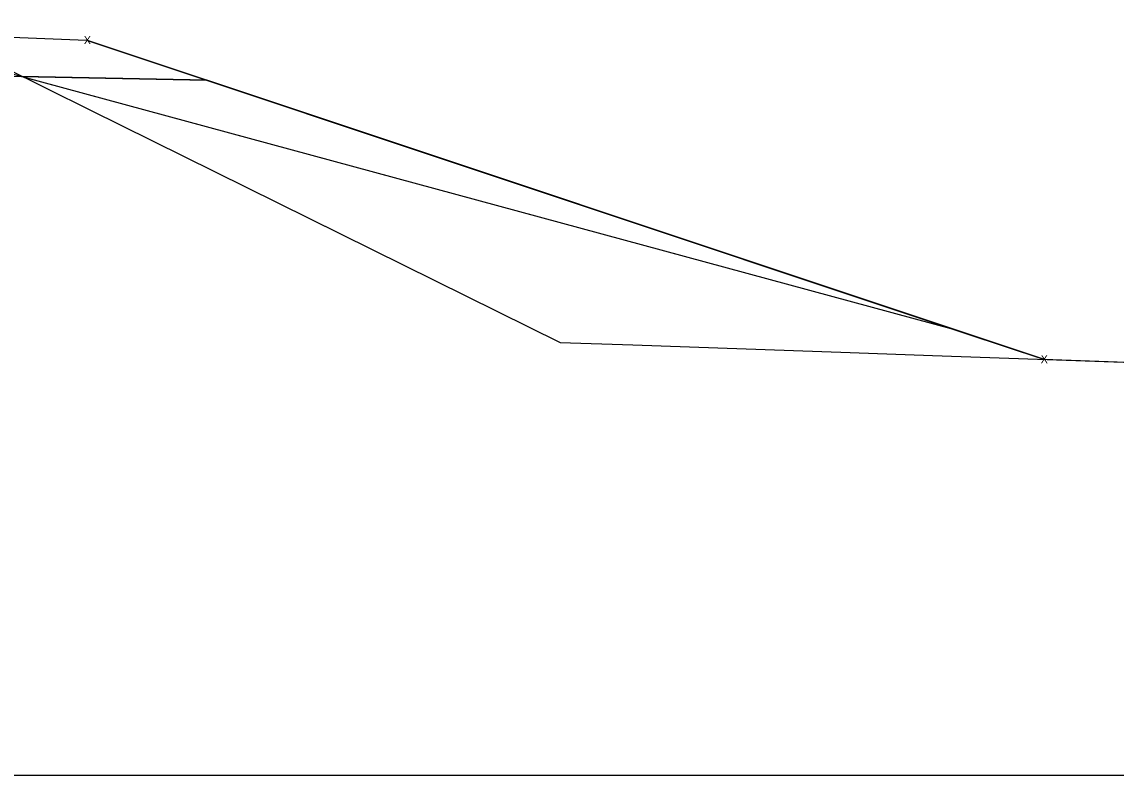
# Model space of a CAD drawing. Extents: x -26 to 303, y -16 to 6048.
# Drawn here: x 168.4 to 201.2, y 3000 to 3022.57 of the extents above; entities that cross this region are included whole.
import ezdxf

# ---------------------------------------------------------------- set-up
doc = ezdxf.new("R2010")
doc.units = 0
for name, color, linetype in [('DTM_P_FINISHED_GRADE2', 7, 'Continuous'), ('DTM_TEMP_DROP', 7, 'Continuous'), ('DTM_X_GROUND', 7, 'Continuous'), ('XS_CELL', 7, 'Continuous'), ('XS_M_SHAPES_EARTHWORK', 7, 'Continuous'), ('XS_P_GROUND', 7, 'Continuous'), ('XS_P_SHOULDER', 7, 'Continuous'), ('XS_P_SUBGRADE_GRANULAR', 7, 'Continuous')]:
    doc.layers.add(name, color=color, linetype=linetype)

msp = doc.modelspace()

# ---------------------------------------------------------------- linework, layer by layer
at = {"layer": 'DTM_P_FINISHED_GRADE2'}
msp.add_lwpolyline([(100.909, 3012.502), (100.909, 3012.502), (129.436, 3022.011), (136.898, 3022.31), (138.898, 3022.35), (150, 3022.572), (161.342, 3022.345), (163.342, 3022.305), (170.335, 3022.025), (196.584, 3013.275), (199.023, 3012.463)], dxfattribs=at)
at = {"layer": 'DTM_X_GROUND'}
for points in [[(90.987, 3011.993), (100.909, 3012.502), (100.909, 3012.502), (136.898, 3022.31), (136.898, 3022.31), (138.898, 3022.35), (138.898, 3022.35), (150, 3022.572), (161.342, 3022.345), (161.342, 3022.345), (163.342, 3022.305), (163.342, 3022.305), (163.342, 3022.305), (196.361, 3013.35), (196.584, 3013.275), (196.704, 3013.235), (199.023, 3012.463), (199.023, 3012.463), (199.023, 3012.463), (199.023, 3012.463), (199.023, 3012.463), (204.279, 3012.279)], [(90.297, 3011.958), (114.375, 3013.193), (115.641, 3013.245), (117.971, 3014.259), (136.605, 3021.412), (136.898, 3021.446), (141.492, 3021.538), (149.994, 3021.716), (159.289, 3021.672), (163.342, 3021.651), (165.342, 3021.457), (167.862, 3021.214), (170.435, 3019.941), (184.541, 3012.969), (186.717, 3012.893), (193.229, 3012.665), (195.696, 3012.579), (204.279, 3012.279)]]:
    msp.add_lwpolyline(points, dxfattribs=at)
at = {"layer": 'XS_CELL'}
msp.add_line((150, 3000), (300, 3000), dxfattribs=at)
at = {"layer": 'XS_M_SHAPES_EARTHWORK'}
msp.add_lwpolyline([(168.401, 3020.933), (196.359, 3013.35), (173.945, 3020.822)], close=True, dxfattribs=at)
at = {"layer": 'XS_P_GROUND'}
msp.add_lwpolyline([(199.023, 3012.463), (170.335, 3022.025), (170.335, 3022.025)], dxfattribs=at)
at = {"layer": 'XS_P_SHOULDER'}
msp.add_lwpolyline([(163.342, 3022.305), (170.335, 3022.025)], dxfattribs=at)
at = {"layer": 'XS_P_SUBGRADE_GRANULAR'}
msp.add_lwpolyline([(163.342, 3021.034), (165.342, 3020.994), (173.945, 3020.822)], dxfattribs=at)

# ---------------------------------------------------------------- texts
at = {"layer": 'DTM_TEMP_DROP'}
msp.add_text('X', height=0.24, dxfattribs=at).set_placement((198.944, 3012.343))
at = {"layer": 'XS_P_GROUND'}
msp.add_text('X', height=0.24, dxfattribs=at).set_placement((170.257, 3021.905))
at = {"layer": 'XS_P_SUBGRADE_GRANULAR'}
msp.add_text('X', height=0.24, dxfattribs=at).set_placement((198.944, 3012.343))

doc.saveas('drawing.dxf')
